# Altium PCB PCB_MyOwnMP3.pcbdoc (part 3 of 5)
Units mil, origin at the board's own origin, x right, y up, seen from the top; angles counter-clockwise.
Board outline 3605 x 4860 mil, 6 copper layers (Top Layer, Inner1, Inner2, Inner3, Inner4, Bottom Layer); 291 components, 261 nets, 1070 pads, 1658 vias.
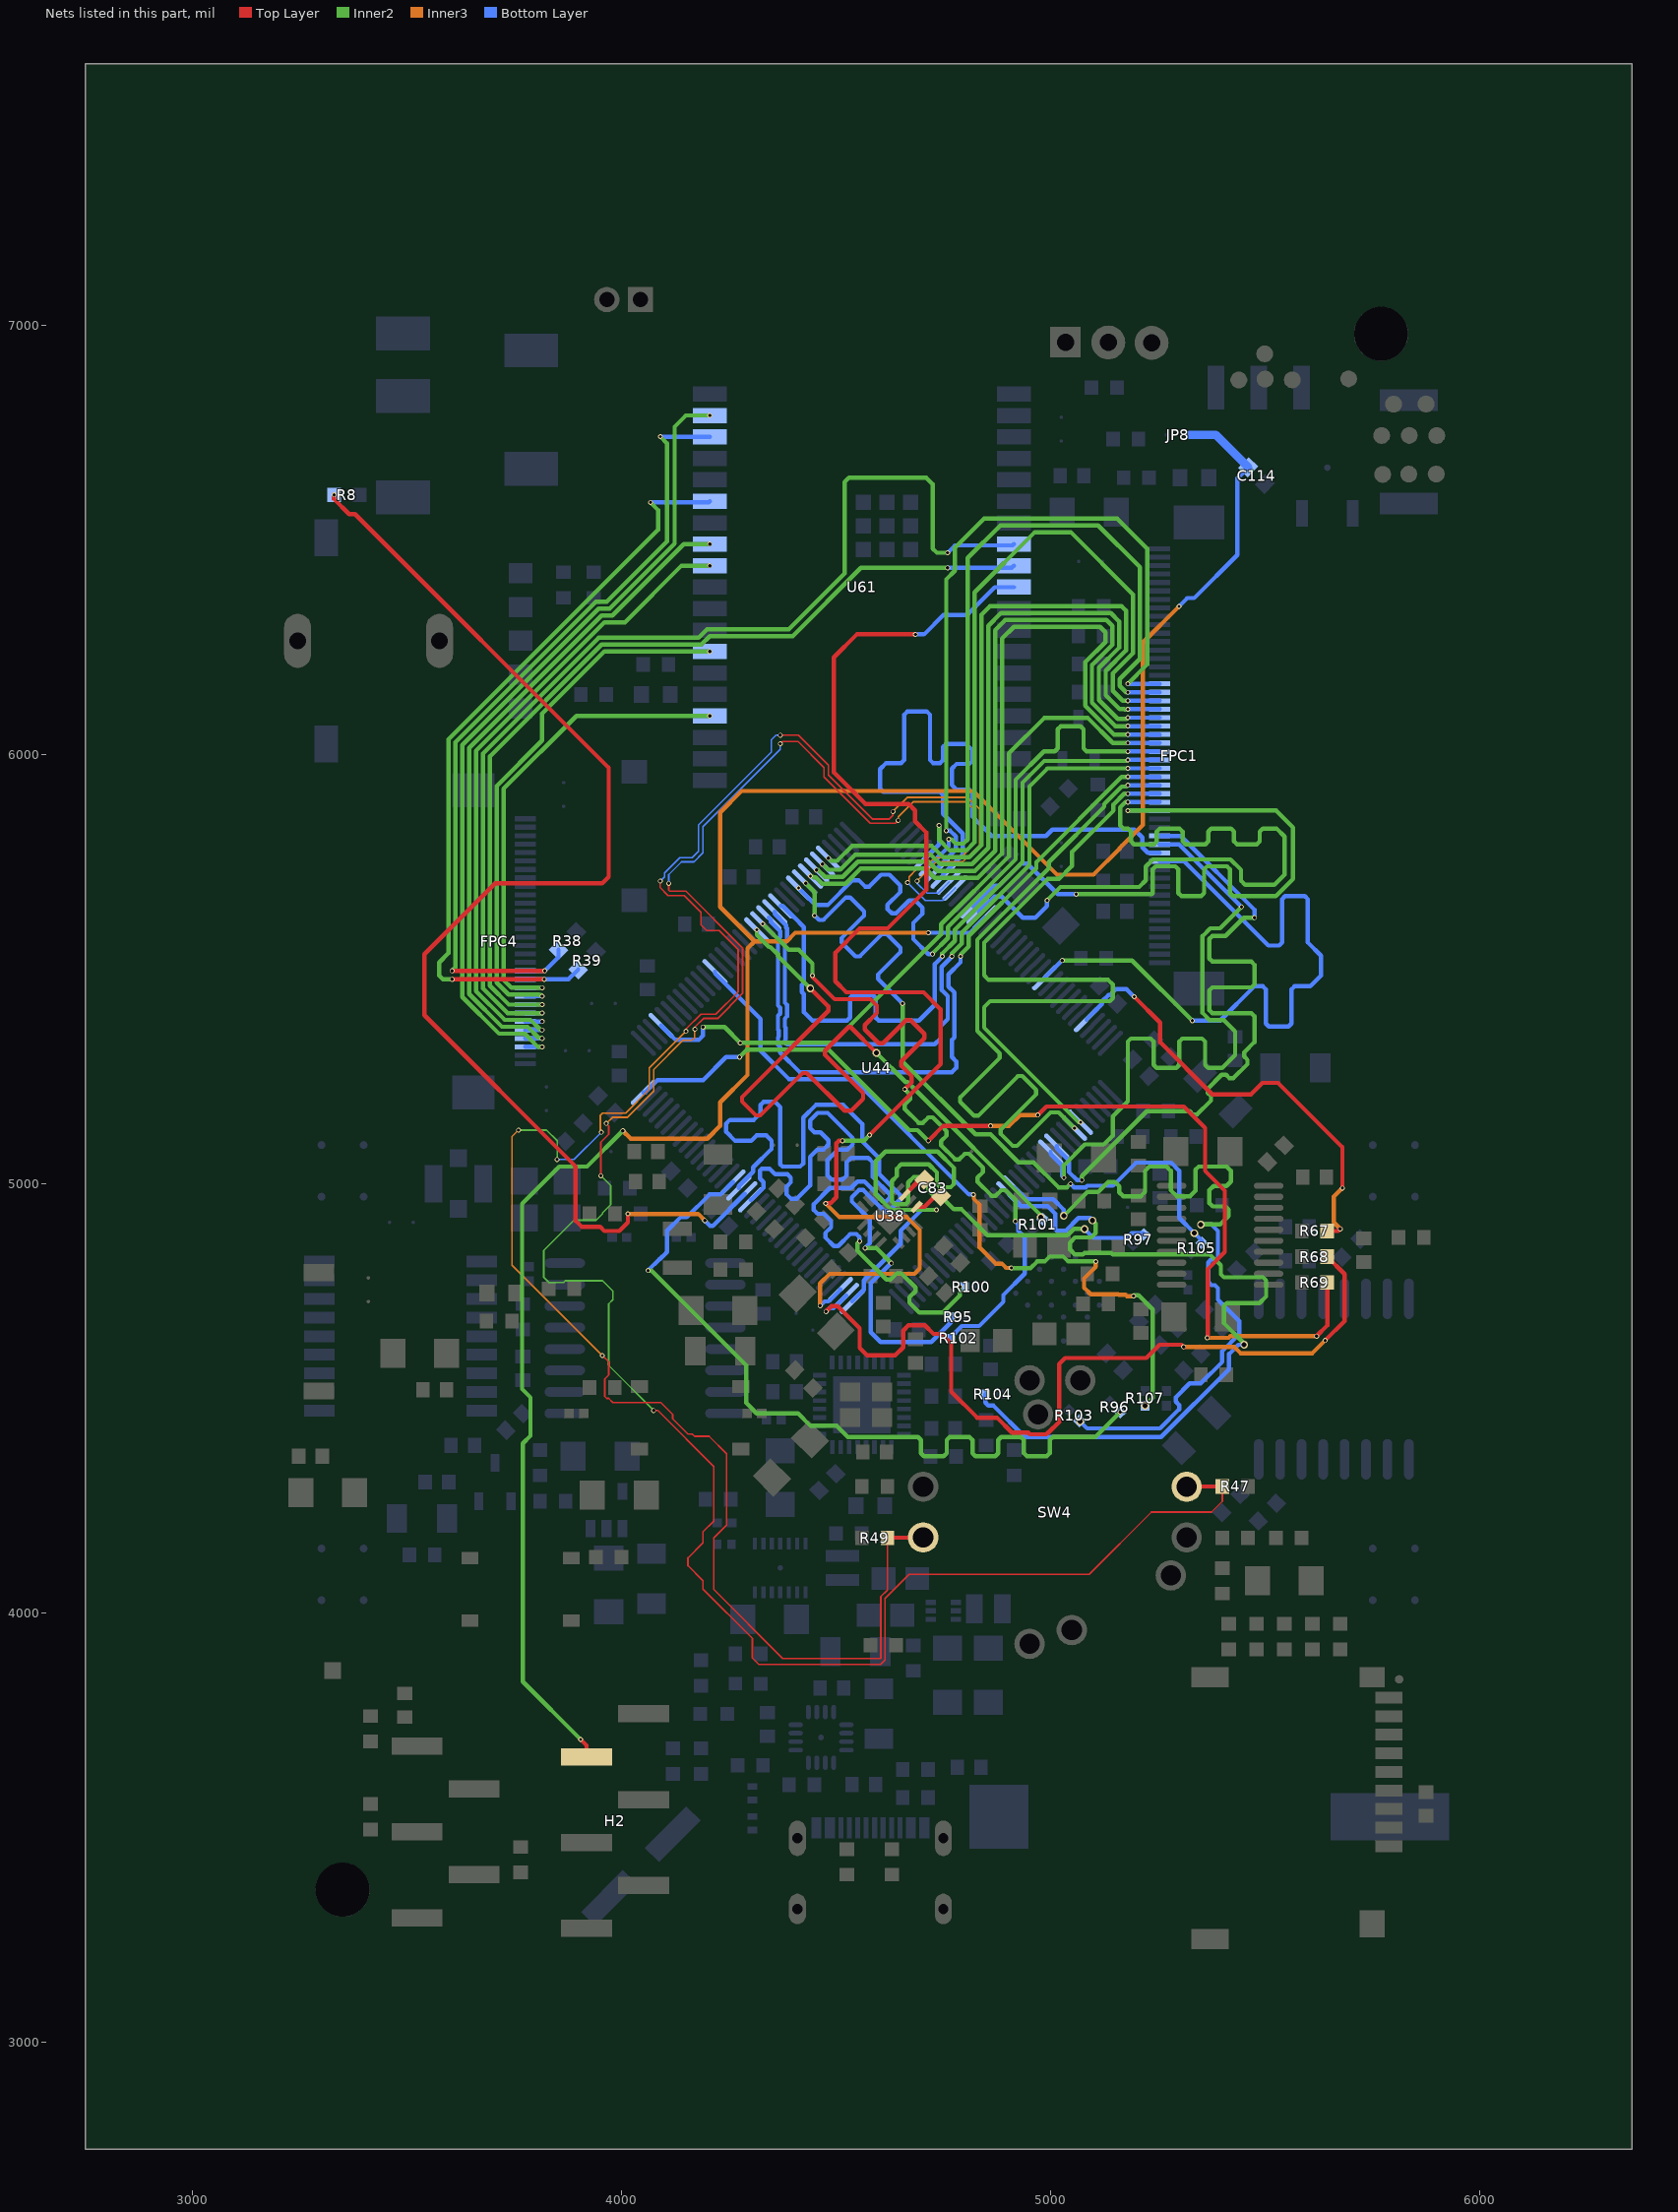
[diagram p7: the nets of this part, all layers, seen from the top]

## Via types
v1: diameter 11.42, hole 7.48, Top Layer to Bottom Layer, 1536 vias
v2: diameter 17.72, hole 11.81, Top Layer to Bottom Layer, 85 vias
v3: diameter 39.37, hole 29.53, Top Layer to Bottom Layer, 11 vias
v4: diameter 11.81, hole 7.87, Top Layer to Bottom Layer, 8 vias
v5: diameter 47.24, hole 23.62, Top Layer to Bottom Layer, 8 vias
v6: diameter 19.68, hole 11.81, Top Layer to Bottom Layer, 4 vias
v7: diameter 24.41, hole 12.2, Top Layer to Bottom Layer, 3 vias
v8: diameter 11.4, hole 7.5, Top Layer to Bottom Layer, 3 vias

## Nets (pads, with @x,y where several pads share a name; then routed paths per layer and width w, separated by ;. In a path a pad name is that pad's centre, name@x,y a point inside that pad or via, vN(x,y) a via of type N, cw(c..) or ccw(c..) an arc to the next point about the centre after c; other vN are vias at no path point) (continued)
CK#: R107.1 U44.49 | length 1785.5
  Inner2 w10: v1(4908.62,4803.99) 4909.38,4803.23 4953.03,4803.23 4968.81,4819.02 4986.07,4819.02 4997.45,4830.39 5029.61,4830.39 5040.98,4819.02 5104.96,4819.02 v1(5105.27,4818.7) ; v1(5193.31,4738.31) 5195,4740 5205,4740 5238.03,4706.97 5238.03,4500.99 v2(5220,4482.96)
  Inner3 w10: v1(4820,4975) 4821.11,4973.89 4821.11,4964.59 4834.62,4951.08 4834.62,4851.25 4871.88,4813.99 4886.45,4813.99 4896.45,4803.99 v1(4908.62,4803.99) ; v1(5105.27,4818.7) 5105.27,4806.52 5078.05,4779.29 5078.05,4757.74 5093.28,4742.51 5157.63,4742.51 5158.75,4741.38 5174.52,4741.38 5177.6,4738.31 v1(5193.31,4738.31)
  Bottom Layer w10: U44.49@4217.78,5494.1 4217.78,5490.04 4323.94,5383.88 4323.94,5310 4389.92,5244.02 4540.77,5244.02 4809.79,4975 v1(4820,4975)
CPN: C83.1 U38.9 | length 67.1
  Top Layer w10: U38.9@4687.62,4945.9 4705.74,4945.9 4730.35,4970.51 C83.1@4744.49,4970.51
CPP: C83.2 U38.11 | length 60.5
  Top Layer w10: U38.11@4659.83,4973.69 4695.63,5009.49 C83.2@4705.51,5009.49
CS1: FPC4.7 U61.8 | length 2545.3
  Inner2 w10: v1(3815,5397.68) 3734.51,5397.68 3677.05,5455.14 3677.05,6002.26 3946.76,6271.97 4179.36,6271.97 4199.36,6291.97 4390,6291.97 4520,6421.97 4520,6635 4530,6645 4710,6645 4725,6630 4725,6480 4735,6470 v1(4760,6470)
  Bottom Layer w10: FPC4.7@3775.53,5397.68 v1(3815,5397.68) ; v1(4760,6470) 4777.23,6487.23 4911.56,6487.23 U61.8@4914.33,6490
CS2: FPC4.8 U61.9 | length 2119.1
  Inner2 w10: v1(3815,5417.36) 3737.43,5417.36 3693.03,5461.76 3693.03,5995.64 3953.38,6255.98 4185.98,6255.98 4205.98,6275.98 4399.02,6275.98 4558.03,6435 v1(4760,6435)
  Bottom Layer w10: FPC4.8@3775.53,5417.36 v1(3815,5417.36) ; v1(4760,6435) 4909.33,6435 U61.9@4914.33,6440
CS3: FPC4.9 U61.26 | length 1279.7
  Inner2 w10: v1(3815,5437.05) 3812.01,5440.04 3808.09,5440.04 3807.38,5440.75 3736.65,5440.75 3709.02,5468.38 3709.02,5926.62 3815,6032.6 3815,6095 3960,6240 v1(4205.67,6240)
  Bottom Layer w10: FPC4.9@3775.53,5437.05 v1(3815,5437.05)
CS4: FPC4.10 U61.23 | length 1133.1
  Inner2 w10: v1(3815,5456.73) 3743.27,5456.73 3725,5475 3725,5920 3895,6090 v1(4205.67,6090)
  Bottom Layer w10: FPC4.10@3775.53,5456.73 v1(3815,5456.73)
CS#: R105.1 U44.64 | length 1823.8
  Inner2 w10: v1(4429.36,5700.11) 4450,5679.47 v1(4450,5625) ; v1(4655,5420) 4655,5285 4825,5115 4860,5115 4925,5050 4960,5050 5018.34,4991.66 5038.05,4991.66 v1(5046.39,5000)
  Bottom Layer w10: v1(4450,5625) 4460.36,5614.64 4470.36,5614.64 4522.86,5667.14 4532.86,5667.14 4565.29,5634.71 4565.29,5624.71 4512.79,5572.21 4512.79,5562.21 4545.21,5529.79 4555.21,5529.79 4607.71,5582.29 4617.71,5582.29 4650.14,5549.86 4650.14,5539.86 4597.64,5487.36 4597.64,5477.36 v1(4655,5420) ; v1(5046.39,5000) 5054.78,4991.61 5081.61,4991.61 5085.35,4995.35 5145.35,4995.35 5199.29,5049.29 5280.71,5049.29 5300,5030 5300,4920 v2(5335,4885) 5352.05,4867.95 R105.1@5352.05,4862.05
DAC_BCK: R69.2 U44.36 | length 2409
  Top Layer w10: v1(4715,5100) 4750,5135 v1(4860,5135) ; v1(4970,5160) 4990,5180 5310,5180 5360,5130 5360,5030 5405.98,4984.02 5405.98,4840.98 5366.69,4801.69 5366.69,4642.68 v1(5365,4640.98) ; v1(5620,4645) 5644.66,4669.66 R69.2@5644.66,4770
  Inner2 w10: v1(4275,5295) 4292.21,5312.21 4482.79,5312.21 4670,5125 4690,5125 v1(4715,5100)
  Inner3 w10: v1(4860,5135) 4903.32,5135 4928.32,5160 v1(4970,5160) ; v1(5365,4640.98) 5415,4640.98 5419.02,4645 v1(5620,4645)
  Bottom Layer w10: U44.36@4050.75,5212.93 4055.26,5212.93 4083.84,5241.51 4190.41,5241.51 4243.9,5295 v1(4275,5295)
DAC_DIN: R68.2 U44.2 | length 1946.1
  Top Layer w10: v1(4476.58,4702.21) 4489.43,4715.06 4503.57,4715.06 4555.04,4663.6 4555.04,4617.35 4572.28,4600.11 4637.72,4600.11 4656.3,4618.69 4656.3,4657.86 4668.44,4670 4707.09,4670 4726.96,4650.13 4746.52,4650.13 4768.41,4628.24 4768.41,4515.37 4828.78,4455 4875,4455 4910,4420 4947.55,4420 4951.4,4416.14 4989.86,4416.14 4993.71,4420 4995,4420 5020,4445 5020,4580 5034.02,4594.02 5223.18,4594.02 5254.16,4625 5305,4625 v1(5310,4620) ; v1(5640,4635) 5685,4680 5685,4789.66 R68.2@5644.66,4830
  Inner3 w10: v1(5310,4620) 5427.92,4620 5442.77,4605.16 5610.16,4605.16 v1(5640,4635)
  Bottom Layer w10: v1(4476.58,4702.21) 4484.37,4710 4494.34,4710 U44.2@4524.01,4739.67
DAC_LRCK: R67.2 U44.104 | length 1067.4
  Top Layer w10: v1(5195,5435.72) 5255,5375.72 5255,5330 5376.69,5208.31 5466.91,5208.31 5493.61,5235 5530,5235 5680,5085 v1(5680,4990) ; R67.2@5644.66,4890 5670,4890 v1(5675,4895)
  Inner3 w10: v1(5675,4895) 5660,4910 5660,4970 v1(5680,4990)
  Bottom Layer w10: U44.104@5083.58,5382.75 5120,5419.17 5120,5425 5135,5440 5138.96,5440 5152.22,5453.26 5176.74,5453.26 5194.28,5435.72 v1(5195,5435.72)
DETECT: R8.1 U44.19 | length 2908.8
  Top Layer w10: v1(3330,6605) 3330,6595 3365,6560 3379.14,6560 3970,5969.14 3970,5715 3955,5700 3705.83,5700 3540.83,5535 3540.83,5392.55 3893.15,5040.22 3893.15,4913.77 3906.92,4900 3950,4900 3960,4890 3995,4890 4015,4910 v1(4015,4929.8)
  Inner3 w10: v1(4015,4929.8) 4178.61,4929.8 v1(4194.16,4914.25)
  Bottom Layer w10: v1(4194.16,4914.25) 4206.52,4901.89 4213.06,4901.89 U44.19@4287.38,4976.21
DQ0: R95.2 U44.20 | length 1906.6
  Inner2 w10: v1(4567.63,4850.06) 4593.73,4850.06 v1(4628.81,4814.98)
  Bottom Layer w10: U44.20@4273.46,4990.22 4273.46,4994.72 4306.94,5028.21 4306.94,5038.48 4349.66,5081.2 4349.66,5100.34 4337.45,5112.55 4314.75,5112.55 4302.19,5100 4265,5100 4243.75,5121.25 4243.75,5140 4252.51,5148.75 4308.46,5148.75 4324.2,5164.5 4324.2,5184.2 4331.09,5191.09 4357.55,5191.09 4370,5178.63 4370,5045 4375,5040 4416.39,5040 4423.46,5047.07 4423.46,5154.12 4452.99,5183.65 4516.64,5183.65 4561.27,5139.01 4561.27,5098.73 4600.98,5059.02 4600.98,5022.5 4649.81,4973.67 4649.81,4963.67 4622.39,4936.25 4612.39,4936.25 4563.37,4985.27 4553.37,4985.27 4536.66,4968.56 4536.66,4958.56 4578.61,4916.61 4578.61,4861.04 v1(4567.63,4850.06) ; v1(4628.81,4814.98) 4627.8,4814.98 4580.98,4768.16 4580.98,4654.02 4603.7,4631.3 4721.96,4631.3 4767.96,4677.3 R95.2@4767.96,4690
DQ1: R96.2 U44.21 | length 1867.8
  Inner2 w10: v1(4062.16,4797.84) 4069.55,4797.84 4290.47,4576.92 4290.47,4489.53 4315,4465 4411.4,4465 4440.41,4435.98 4501.62,4435.98 4527.61,4410 4690.76,4410 4697.83,4402.93 4697.83,4372.07 4704.9,4365 4750.76,4365 4757.83,4372.07 4757.83,4402.93 4764.9,4410 4810.76,4410 4817.83,4402.93 4817.83,4372.07 4824.9,4365 4870.76,4365 4877.83,4372.07 4877.83,4402.93 4884.9,4410 4930.76,4410 4937.83,4402.93 4937.83,4372.07 4944.9,4365 4990.76,4365 4997.83,4372.07 4997.83,4402.93 5004.9,4410 5104.1,4410 v1(5162.05,4467.95)
  Bottom Layer w10: v1(4062.16,4797.84) 4088.03,4823.71 4088.71,4823.71 4105.24,4840.24 4105.24,4840.92 4105.84,4841.52 4105.84,4890.18 4137.51,4921.85 4151.85,4921.85 4205,4975 4230.41,4975 U44.21@4259.54,5004.13
DQ2: R97.2 U44.1 | length 1783.1
  Inner2 w10: v1(4734.13,4939.28) 4628.33,4939.28 4592.11,4975.5 4592.11,5052.11 4615,5075 4736.73,5075 4775,5036.73 4775,4999.75 4767.05,4991.79 4742.07,4991.79 4735,4998.86 4735,5026.35 4716.35,5045 4651.62,5045 4641.86,5035.24 4641.86,5018.25 4630,5006.39 4630,4959.2 4637.13,4952.07 4662.07,4952.07 4667.93,4957.93 4667.93,5002.93 4681.04,5016.04 4701.81,5016.04 4715,5002.85 4715,4985 4725,4975 4740,4975 4774.4,4940.6 4792.49,4940.6 4852.75,4880.33 5039.67,4880.33 5054.33,4895 5078.54,4895 v2(5078.85,4894.69)
  Bottom Layer w10: U44.1@4537.93,4725.75 4565,4752.82 4565,4774.78 4650.98,4860.77 4650.98,4890.77 4699.49,4939.28 v1(4734.13,4939.28) ; v2(5078.85,4894.69) 5099.6,4873.94 5178.37,4873.94 5188.76,4884.33 5214.77,4884.33 R97.2@5217.05,4882.05
DQ3: R100.2 U44.18 | length 1845.4
  Inner2 w10: v1(4554.8,4866.32) 4549.8,4861.32 4549.8,4844.28 4617.36,4776.71 4627.36,4776.71 4641.99,4791.34 4651.99,4791.34 4685,4758.33 4685,4749.49 4670.98,4735.48 4670.98,4723.09 4694.08,4700 4748.67,4700 4788.26,4739.58 v1@4788.26,4759.95
  Bottom Layer w10: U44.18@4301.3,4962.38 4302.38,4962.38 4330.86,4990.86 4330.86,5004.03 4322.93,5011.96 4322.93,5030.98 4326.95,5035 4345,5035 4357.93,5022.07 4386.72,5022.07 4394.33,5014.45 4394.33,5003.24 4385,4993.91 4385,4975 4394.73,4965.27 4408.87,4965.27 4439.45,4995.84 4439.45,5062.5 4456.95,5080 4471.09,5080 4482.34,5091.25 4482.34,5101.25 4463.59,5120 4449.45,5120 4439.45,5130 4439.45,5147.5 4456.95,5165 4480.36,5165 4538.93,5106.43 4538.93,5091.93 4527,5080 4505,5080 4480,5055 4480,5019.31 4490,5009.31 4515,5009.31 4525,5019.31 4525,5050.36 4535,5060.36 4575,5060.36 4585,5050.36 4585,5015.88 4625.33,4975.55 4625.33,4967.77 4616.36,4958.81 4612.43,4958.81 4566.24,5005 4550,5005 4535,4990 4485.82,4990 4448.11,4952.29 4448.11,4938.96 4457.07,4930 4471.21,4930 4488.54,4912.68 4488.54,4898.54 4475,4885 4475,4875 4495,4855 4505,4855 4533.06,4883.06 4547.2,4883.06 4554.8,4875.46 v1(4554.8,4866.32)
  other v1: 4788.31,4760
DQ4: R101.2 U44.56 | length 1799.6
  Top Layer w10: v2(4440,5455) 4482.03,5412.97 4482.03,5402.97 4280.81,5201.76 4280.81,5191.76 4313.24,5159.33 4323.24,5159.33 4421.89,5257.98 4431.89,5257.98 4519.88,5170 4535.27,5170 4562.93,5197.66 4562.93,5211.8 4474.32,5300.41 4474.32,5310.41 4529,5365.09 4534,5365.09 v2(4594.1,5305)
  Inner2 w10: v1(4315.22,5591.54) 4315.22,5579.78 4343.31,5551.69 4346.91,5551.69 4365,5533.61 4365,5530 v2(4440,5455) ; v2(4594.1,5305) 4662.41,5236.69 4666.91,5236.69 4977.05,4926.56 v2(4977.05,4922.05)
DQ5: R102.2 U44.57 | length 1722.8
  Top Layer w10: v1(4445,5485) 4445,5481.7 4496.7,5430 4580,5430 4595,5415 4595,5397.75 4566.98,5369.73 4566.98,5359.73 4599.4,5327.3 4609.4,5327.3 4663.55,5381.45 4673.55,5381.45 4705.98,5349.02 4705.98,5339.02 4651.83,5284.87 4651.83,5274.87 4676.28,5250.42 4676.28,5236.28 v1(4660,5220)
  Inner2 w10: v1(4329.13,5605.46) 4389.59,5545 4413.06,5545 4445,5513.06 v1(4445,5485) ; v1(4660,5220) 4672.84,5207.16 4672.84,5197.16 4660.01,5184.33 4660.01,5174.33 4692.44,5141.9 4702.44,5141.9 4715.27,5154.73 4725.27,5154.73 4757.7,5122.3 4757.7,5112.3 4744.86,5099.47 4744.86,5089.47 4777.29,5057.05 4787.29,5057.05 4800.12,5069.88 4810.12,5069.88 4842.55,5037.45 4842.55,5027.45 4829.72,5014.62 4829.72,5004.62 4862.14,4972.19 4872.14,4972.19 4884.97,4985.03 4894.97,4985.03 4917.87,4962.13 v1(4917.87,4912.5)
  Bottom Layer w10: R102.2@4767.96,4640 4766.35,4641.61 4793.13,4668.39 4833.39,4668.39 4890,4725 4890,4740.8 4940,4790.8 4940,4875 4925,4890 4925,4905.37 v1(4917.87,4912.5)
DQ6: R103.2 U44.125 | length 1867.8
  Inner2 w10: v2(5030.64,4925.47) 5086.15,4980.98 5110.98,4980.98 5134.02,5004.02 5150,5004.02 5160,4994.02 5160,4980 5169.02,4970.98 5210,4970.98 5220,4980.98 5220,5030 5230,5040 5270,5040 5280,5030 5280,4985 5294.02,4970.98 5325,4970.98 5337.93,4983.91 5337.93,5032.93 5345,5040 5410,5040 5420,5030 5420,5005 5410,4995 5380,4995 5370,4985 5370,4955 5377.93,4947.07 5407.93,4947.07 5415,4940 5415,4925 5395,4905 v2(5350,4905)
  Bottom Layer w10: U44.125@4916.54,4990.22 4943.07,4963.69 5006.31,4963.69 5030.64,4939.36 v2(5030.64,4925.47) ; v2(5068.92,4446.08) 5085,4430 5255,4430 5299.45,4474.45 5299.45,4484.45 5291.61,4492.28 5291.61,4502.28 5324.04,4534.71 5349.71,4534.71 5400,4585 5400,4610 5440,4650 5440,4680 5390,4730 5390,4756.78 5382.93,4763.85 5374.42,4763.85 5367.35,4770.92 5367.35,4816.78 5374.42,4823.85 5386.25,4823.85 5390,4827.61 5390,4890 5375,4905 v2(5350,4905)
DQ7: R104.2 U44.126 | length 1906.4
  Inner2 w10: v2(5097.55,4914.46) 5105,4907.02 5105,4885 5094.84,4874.84 5056.78,4874.84 5045,4863.06 5045,4846.94 5056.82,4835.12 5075.12,4835.12 5078.96,4838.96 5141.04,4838.96 5144.88,4835.12 5371.66,4835.12 5396.78,4810 5396.78,4789.02 5403.85,4781.95 5495.22,4781.95 5502.29,4774.88 5502.29,4737.29 5486.95,4721.95 5410.92,4721.95 5403.85,4714.88 5403.85,4675.18 5450.98,4628.05 v2(5450.98,4625)
  Bottom Layer w10: R104.2@4847.96,4510 4847.96,4490 4855.03,4482.93 4867.07,4482.93 4940,4410 5257.61,4410 5415.98,4568.38 5415.98,4603.38 5437.61,4625 v2(5450.98,4625) ; U44.126@4902.62,4976.3 4931.21,4947.71 4993.09,4947.71 5010.79,4930 5010.79,4894.21 5014.17,4890.83 5035.83,4890.83 5065,4920 5092.02,4920 v2@5097.53,4914.49
ENC_A: R49.1 SW4.8 U44.81 | length 4820.5
  Top Layer w3.94: v1(3955,4600) 3970,4585 3970,4554.47 3960.83,4545.3 3960.83,4504.7 3965.49,4500.04 3970,4500.04 ; 3970,4500 3980,4490 4091.68,4490 4119.37,4462.31 4119.37,4452.31 4154.63,4417.05 4164.63,4417.05 4169.97,4411.71 4203.96,4411.71 4245,4370.68 4245,4205 4215,4175 4215,4055 4375.83,3894.17 4604.17,3894.17 4604.17,4038.2 4619.66,4053.69 R49.1@4619.66,4175 ; v1(4090.04,5704.96) 4090.04,5690.22 4108.67,5671.59 4146.06,5671.59 4185,5632.65 4185,5603.24 4198.24,5590 4227.65,5590 4271.99,5545.66 4271.99,5447.16 4219.8,5394.96 4184.96,5394.96 4150,5360 v1(4150,5355) ; v1(4370,6045) 4412.05,6045 4482.05,5975 4482.05,5951.98 4584.11,5849.92 4624.44,5849.92 4632.68,5858.16 v1(4632.68,5867.32)
  Top Layer w10: R49.1@4619.6,4175 SW4.8@4702.91,4175.94
  Inner2 w3.94: v1(3760,5125) 3825,5125 3850,5100 v1(3850,5056.69)
  Inner3 w3.94: v1(3760,5125) 3745,5110 3745,4810 v1(3955,4600) ; v1(3952.95,5120) 3950.83,5122.12 3950.83,5159.73 3955.55,5164.45 4009.45,5164.45 4065,5220 4065,5270 v1(4150,5355) ; v1(4632.68,5867.32) 4665.36,5900 4807.05,5900 4835,5872.05 4835,5790 4795,5750 4733.65,5750 v1(4688.88,5705.23)
  Bottom Layer w3.94: v1(3850,5056.69) 3889.65,5056.69 v1(3952.95,5120) ; v1(4090.04,5704.96) 4100.08,5715 4100.08,5724.11 4135.89,5759.92 4164.63,5759.92 4179.7,5775 4179.7,5836.08 4349.31,6005.69 4349.31,6034.31 4360,6045 v1(4370,6045) ; v1(4688.88,5705.23) 4688.88,5700.15 4712.02,5677.02 4737.55,5677.02 U44.81@4763.43,5702.9
ENC_B: R47.1 SW4.7 U44.82 | length 5450.3
  Top Layer w3.94: v1(3951.69,5018.7) 3951.69,5096.69 3970,5115 3970,5135 v1(3964.5,5140.5) ; v1(4075,4471.69) 4084.78,4471.69 4215.12,4341.35 4215.12,4214.15 4190.08,4189.11 4190.08,4163.46 4155,4128.38 4155,4110 4190,4075 4190,4055.97 4305,3940.97 4305,3895 4319.92,3880.08 4604.11,3880.08 4614.09,3890.06 4614.09,4034.09 4670,4090 5090,4090 5235,4235 5375,4235 5400.34,4260.34 R47.1@5400.34,4295 ; v1(4110,5700) 4110,5684.29 4112.78,5681.51 4150.17,5681.51 4281.91,5549.77 4281.91,5443.05 4223.91,5385.04 4190.72,5385.04 4171.34,5365.66 v1(4171.34,5360.02) ; v1(4370,6025) 4375.08,6030.08 4411.51,6030.08 4472.13,5969.46 4472.13,5947.87 4580,5840 4638.31,5840 v1(4645,5846.69)
  Top Layer w10: SW4.7@5317.1,4294.1 R47.1@5400.34,4295
  Inner2 w3.94: 3818.5,4784.61 3818.59,4784.52 ; v1(3951.69,5018.7) 3974.65,4995.75 3974.65,4951.5 3955.51,4932.36 3955.51,4930 3940.51,4915 3889.49,4915 3818.59,4844.1 3818.59,4784.52 ; v1(4075,4471.69) 3970,4576.69 3970,4720 3980,4730 3980,4750 3955.89,4774.11 3869.11,4774.11 3865,4770 3830.93,4770 3818.59,4782.33 3818.59,4784.52
  Inner3 w3.94: v1(3964.5,5140.5) 3978.52,5154.53 4013.56,5154.53 4074.92,5215.89 4074.92,5265.89 4143.12,5334.09 4164.09,5334.09 4170,5340 4170,5358.68 v1(4171.34,5360.02) ; v1(4645,5846.69) 4645,5855 4679.65,5889.65 4803.37,5889.65 4825.08,5867.94 4825.08,5794.52 4790.48,5759.92 4729.54,5759.92 4702.31,5732.69 4687.69,5732.69 4670,5715 4670,5705 v1(4666.54,5701.54)
  Bottom Layer w3.94: v1(4110,5700) 4110,5720 4140,5750 4168.74,5750 4189.63,5770.89 4189.63,5831.97 4370,6012.35 v1(4370,6025) ; v1(4666.54,5701.54) 4708.07,5660 4748.38,5660 U44.82@4777.35,5688.97
ESP32_EN: C114.2 H2.5 JP8.2 U44.87 | length 5520.2
  Top Layer w10: v1(3905,3705) 3918.46,3691.54 H2.5@3918.46,3665
  Inner2 w10: v1(3905,3705) 3770,3840 3770,4395 3787.94,4412.94 3787.94,4502.06 3768.31,4521.69 3768.31,4953.31 3855,5040 3919.78,5040 v1(4003.09,5123.31)
  Inner3 w10: v1(4003.09,5123.31) 4021.51,5104.89 4199.89,5104.89 4230,5135 4230,5190 4293.5,5253.5 4293.5,5548.5 4310,5565 ; v1(4715.26,5584.8) 4404.8,5584.8 4385,5565 4310,5565 ; v1(5299.02,6345) 5215,6260.98 5215,5836.05 5160.87,5781.91 5160.87,5780.87 5100,5720 5015,5720 4820,5915 4280,5915 4230,5865 4230,5645 4310,5565
  Bottom Layer w10: v1(4715.26,5584.8) 4812.36,5584.8 U44.87@4846.94,5619.38 ; v1(5299.02,6345) 5318.54,6364.53 5334.53,6364.53 5435,6465 5435,6643.98 C114.2@5460.51,6669.49
  Bottom Layer w19.68: JP8.2@5324.53,6745 5385,6745 C114.2@5460.51,6669.49
ESP_CS: FPC4.6 | length 39.5
  Bottom Layer w10: FPC4.6@3775.53,5377.99 v1(3815,5377.99)
ESP_MISO: FPC4.4 U61.31 | length 1583
  Inner2 w10: v1(3815,5338.62) 3813.62,5340 3806.78,5340 3781.07,5365.71 3721.26,5365.71 3645.08,5441.9 3645.08,6015.5 3953.52,6323.94 3978.94,6323.94 4145,6490 4205.43,6490 v1(4205.67,6490.24)
  Bottom Layer w10: FPC4.4@3775.53,5338.62 v1(3815,5338.62)
ESP_MOSI: FPC4.3 U61.37 | length 1914.6
  Inner2 w10: v1(3815,5318.94) 3805.23,5318.94 3774.45,5349.73 3714.64,5349.73 3629.1,5435.28 3629.1,6022.12 3946.9,6339.92 3972.32,6339.92 4123.7,6491.3 4123.7,6763.7 4150,6790 v1(4205.67,6790)
  Bottom Layer w10: FPC4.3@3775.53,5318.94 v1(3815,5318.94)
ESP_SCK: FPC4.5 U61.30 | length 1514.3
  Inner2 w10: v1(3815,5358.31) 3811.07,5358.31 3787.69,5381.7 3727.88,5381.7 3661.06,5448.52 3661.06,6008.88 3960.14,6307.95 4007.95,6307.95 4140,6440 v1(4205.67,6440)
  Bottom Layer w10: FPC4.5@3775.53,5358.31 v1(3815,5358.31)
ESP_SCL: FPC4.12 R38.2 U61.36 | length 1912.7
  Top Layer w10: v1(3605,5496.1) v1(3821.1,5496.1)
  Inner2 w10: v1(3605,5496.1) 3613.11,5504.21 3613.11,6028.74 3940.28,6355.9 3965.69,6355.9 4106.25,6496.46 4106.25,6725 v1(4090.63,6740.63)
  Bottom Layer w10: FPC4.12@3775.53,5496.1 v1(3821.1,5496.1) 3853.1,5528.1 R38.2@3853.07,5544.99 ; v1(4090.63,6740.63) 4091.25,6740 U61.36@4205.67,6740
ESP_SDA: FPC4.11 R39.2 U61.33 | length 1841.7
  Top Layer w10: v1(3605,5476.4) v1(3820.09,5476.4)
  Inner2 w10: v1(3605,5476.4) 3583.6,5476.4 3575,5485 3575,5515.37 3597.13,5537.5 3597.13,6035.36 4085,6523.23 4085,6570 v1(4067.5,6587.5)
  Bottom Layer w10: FPC4.11@3775.53,5476.42 v1(3820.09,5476.4) 3876.4,5476.4 R39.2@3899.03,5499.03 ; v1(4067.5,6587.5) 4203.17,6587.5 U61.33@4205.67,6590
FMC_A16: FPC1.37 U44.80 | length 1639.3
  Bottom Layer w10: U44.80@4749.51,5716.81 4749.51,5721.05 4795.18,5766.72 4795.18,5816.03 4749.51,5861.7 4749.51,5906.12 4742.44,5913.19 4609.62,5913.19 4602.55,5920.26 4602.55,5966.12 4616.69,5980.26 4651.85,5980.26 4658.92,5987.33 4658.92,6092.93 4665.99,6100 4711.85,6100 4718.92,6092.93 4718.92,5987.33 4725.99,5980.26 4742.44,5980.26 4749.51,5987.33 4749.51,6017.93 4756.58,6025 4802.93,6025 4817.93,6010 4817.93,5985.25 4810.86,5978.18 4780.89,5978.18 4770,5967.29 4770,5929.08 4780.89,5918.18 4810.86,5918.18 4817.93,5911.11 4817.93,5855.51 4863.44,5810 4988.94,5810 5004.14,5825.2 5195.13,5825.2 5213.76,5806.57 5213.76,5783.85 5226.62,5770.98 FPC1.37@5254.35,5770.98
FMC_D0: FPC1.32 U44.85 | length 1672.3
  Inner2 w10: v1(5059.49,5674.74) 5235.45,5674.74 5237.79,5677.07 5237.79,5732.62 5244.86,5739.69 5290.72,5739.69 5297.79,5732.62 5297.79,5677.07 5304.86,5670 5350.72,5670 5357.79,5677.07 5357.79,5732.62 5364.86,5739.69 5410.72,5739.69 5417.79,5732.62 5417.79,5677.07 5424.86,5670 5525,5670 5565,5710 5565,5830 5525.59,5869.41 v1(5180,5869.41)
  Bottom Layer w10: U44.85@4819.1,5647.22 4866.41,5694.53 4879.53,5694.53 4931.13,5746.13 4945.27,5746.13 5016.66,5674.74 v1(5059.49,5674.74) ; v1(5180,5869.41) FPC1.32@5254.35,5869.41
FMC_D1: FPC1.31 U44.86 | length 1672.5
  Inner2 w10: v1(4991.69,5660.22) 5022.9,5691.43 5206.43,5691.43 5221.8,5706.8 5221.8,5739.24 5238.24,5755.67 5419.33,5755.67 5443.7,5731.3 5443.7,5706.15 5453.62,5696.23 5521.23,5696.23 5545,5720 5545,5809.02 5526.3,5827.72 5494.56,5827.72 5487.48,5820.65 5487.48,5797.83 5480.41,5790.76 5434.56,5790.76 5427.48,5797.83 5427.48,5820.65 5420.41,5827.72 5374.56,5827.72 5367.48,5820.65 5367.48,5797.83 5360.41,5790.76 5314.56,5790.76 5307.48,5797.83 5307.48,5820.65 5300.41,5827.72 5254.56,5827.72 5247.48,5820.65 5247.48,5797.83 5240.41,5790.76 5194.56,5790.76 5187.48,5797.83 5187.48,5820.65 5180.41,5827.72 5169.49,5827.72 5162.42,5834.79 5162.42,5877 5174.51,5889.09 v1(5180,5889.09)
  Bottom Layer w10: U44.86@4833.03,5633.3 4868.91,5669.18 4885.82,5669.18 4935,5620 4964.19,5620 4991.69,5647.5 v1(4991.69,5660.22) ; v1(5180,5889.09) FPC1.31@5254.35,5889.09
FMC_D2: FPC1.30 U44.114 | length 1669.5
  Inner2 w10: v1(5069.65,5143.33) 5065.43,5143.33 4845,5363.76 4845,5411.38 4859.14,5425.52 5137.9,5425.52 5144.97,5432.59 5144.97,5464.31 5134.28,5475 4855.52,5475 4845,5485.52 4845,5561.84 4993.16,5710 5019.48,5710 5050,5740.52 5050,5773.04 5146.44,5869.48 5146.44,5883.62 5171.59,5908.78 v1(5180,5908.78)
  Bottom Layer w10: v1(5180,5908.78) FPC1.30@5254.35,5908.78
FMC_D3: FPC1.29 U44.115 | length 1634.4
  Inner2 w10: v1(5055.74,5129.41) 5018.91,5166.24 4999.85,5166.24 4921.8,5088.2 4911.8,5088.2 4883.91,5116.09 4883.91,5126.09 4966.48,5208.67 4966.48,5218.67 4934.06,5251.09 4924.06,5251.09 4831.48,5158.52 4821.48,5158.52 4789.06,5190.94 4789.06,5200.94 4881.63,5293.52 4881.63,5303.52 4829.02,5356.13 4829.02,5568.46 4995.82,5735.27 4995.82,5749.41 5125,5878.58 5125,5884.79 5165.68,5925.47 5177.01,5925.47 v1(5180,5928.46)
  Bottom Layer w10: v1(5180,5928.46) FPC1.29@5254.35,5928.46
FMC_D4: FPC1.28 U44.58 | length 1715
  Inner2 w10: v1(4790,5530) 4790,5533.95 4808.94,5552.89 4808.94,5577.19 4966.61,5734.86 4966.61,5749 5165.75,5948.15 v1(5180,5948.15)
  Bottom Layer w10: U44.58@4343.06,5619.38 4348.06,5614.38 4348.06,5610.14 4350.82,5607.37 4350.82,5607.1 4369.57,5588.35 4369.57,5574.69 4364.57,5569.69 4364.57,5415.26 4369.57,5410.26 4369.57,5396.43 4364.57,5391.43 4364.57,5359.04 4366.69,5356.91 4366.69,5343.09 4364.57,5340.96 4364.57,5323.38 4369.57,5318.38 4369.57,5305.43 4415,5260 4770,5260 4780.08,5270.08 4780.08,5284.92 4770,5295 4770,5335 4776.16,5341.16 4776.16,5445.23 4761.97,5459.42 4761.97,5487.83 4790,5515.86 v1(4790,5530) ; v1(5180,5948.15) FPC1.28@5254.35,5948.15
FMC_D5: FPC1.27 U44.59 | length 1699.6
  Inner2 w10: v1(4770,5530) 4770,5536.56 4792.95,5559.51 4792.95,5585.02 4950.62,5742.69 4950.62,5925.62 4992.83,5967.83 v1(5180,5967.83)
  Bottom Layer w10: U44.59@4356.97,5633.3 4356.97,5628.8 4383.5,5602.27 4383.5,5597.03 4385.55,5594.97 4385.55,5568.06 4380.55,5563.06 4380.55,5421.88 4385.55,5416.88 4385.55,5389.81 4380.55,5384.81 4380.55,5365.66 4382.68,5363.54 4382.68,5336.46 4380.55,5334.34 4380.55,5330 4385.55,5325 4730,5325 4744.09,5339.09 4744.09,5367.3 4760.18,5383.38 4760.18,5437.43 4745.98,5451.62 4745.98,5504.98 4770,5528.99 v1(4770,5530) ; v1(5180,5967.83) FPC1.27@5254.35,5967.83
FMC_D6: FPC1.26 U44.60 | length 1652.9
  Inner2 w10: v1(4747.4,5530) 4747.4,5536.56 4776.97,5566.13 4776.97,5591.64 4934.64,5749.31 4934.64,5934.64 4985,5985 5177.48,5985 v1(5180,5987.52)
  Bottom Layer w10: U44.60@4370.9,5647.22 4375.4,5647.22 4401.92,5620.7 4402.42,5620.7 4425,5598.12 4425,5468.06 4420.16,5463.22 4420.16,5446.78 4425,5441.94 4425,5400 4445,5380 4525.43,5380 4532.5,5387.07 4532.5,5432.93 4539.57,5440 4585.43,5440 4592.5,5432.93 4592.5,5387.07 4599.57,5380 4693.39,5380 4730,5416.61 4730,5511.6 4747.4,5529 v1(4747.4,5530) ; v1(5180,5987.52) FPC1.26@5254.35,5987.52
FMC_D7: FPC1.25 U44.63 | length 1569.6
  Inner2 w10: v1(4725,5535) 4725,5536.77 4760.98,5572.75 4760.98,5598.26 4918.65,5755.93 4918.65,5941.26 4984.59,6007.2 5009.59,6007.2 5016.67,6014.27 5016.67,6058.88 5023.74,6065.95 5069.59,6065.95 5076.67,6058.88 5076.67,6014.27 5083.74,6007.2 v1(5180,6007.2)
  Bottom Layer w10: v1(4412.65,5688.97) 4452.31,5649.31 4480.6,5649.31 4538.58,5707.28 4552.72,5707.28 4567.57,5692.43 4577.57,5692.43 4605.15,5720 4624.31,5720 4650,5694.31 4650,5680 4620,5650 4620,5640 4630,5630 4640,5630 4670,5660 4684.31,5660 4701.53,5642.78 4701.53,5629.31 4680,5607.78 4680,5570 4715,5535 v1(4725,5535) ; v1(5180,6007.2) FPC1.25@5254.35,6007.2
FMC_D8: FPC1.24 U44.40 | length 1707.4
  Inner2 w10: v1(4190,5365) 4240,5365 v1(4276.8,5328.2) 4492.1,5328.2 4745,5581.1 4745,5604.88 4902.67,5762.55 4902.67,6002.67 4985,6085 5086.9,6085 5145.01,6026.89 v1(5180,6026.89)
  Bottom Layer w10: U44.40@4092.51,5368.83 4126.34,5335 4180,5335 4190,5345 v1(4190,5365) ; v1(5180,6026.89) FPC1.24@5254.35,6026.89
FMC_D9: FPC1.23 U44.65 | length 1651.2
  Inner2 w10: v1(4440.49,5716.81) 4444.73,5716.81 4447.5,5714.05 4452.72,5714.05 4467.75,5699.02 4522.1,5699.02 4557.39,5734.3 4708.21,5734.3 4729.93,5712.58 4830.09,5712.58 4886.69,5769.17 4886.69,6269.84 4914.28,6297.43 5115.23,6297.43 5127.66,6285 5127.66,6262.16 5081.06,6215.56 5081.06,6214.65 5080.44,6214.03 5080.44,6114.06 5147.94,6046.57 v1(5180,6046.57)
  Bottom Layer w10: v1(5180,6046.57) FPC1.23@5254.35,6046.57
FMC_D10: FPC1.22 U44.66 | length 1647.5
  Inner2 w10: v1(4454.41,5730.74) 4458.63,5730.74 4474.37,5715 4515.48,5715 4550.77,5750.29 4714.83,5750.29 4736.55,5728.56 4823.47,5728.56 4870.7,5775.8 4870.7,6289.84 4894.28,6313.41 5130,6313.41 5143.65,6299.77 5143.65,6255.54 5097.05,6208.94 5097.05,6208.03 5096.43,6207.41 5096.43,6120.68 5150.85,6066.26 v1(5180,6066.26)
  Bottom Layer w10: v1(5180,6066.26) FPC1.22@5254.35,6066.26
FMC_D11: FPC1.21 U44.67 | length 1637.1
  Inner2 w10: v1(4468.33,5744.65) 4475.72,5737.26 4476.72,5737.26 4482.4,5731.59 4509.47,5731.59 4544.15,5766.27 4721.45,5766.27 4743.17,5744.55 4816.85,5744.55 4854.72,5782.42 4854.72,6299.72 4884.4,6329.4 5140.6,6329.4 5159.63,6310.37 5159.63,6248.92 5113.03,6202.32 5113.03,6201.41 5112.41,6200.79 5112.41,6131.54 5112.79,6131.16 5112.79,6126.92 5156.38,6083.34 5177.4,6083.34 v1(5180,6085.94)
  Bottom Layer w10: v1(5180,6085.94) FPC1.21@5254.35,6085.94
FMC_D12: FPC1.20 U44.68 | length 1638.7
  Inner2 w10: v1(4482.25,5758.57) 4488.63,5752.19 4502.46,5752.19 4537.14,5786.87 4723.45,5786.87 4749.79,5760.53 4810.23,5760.53 4838.73,5789.04 4838.73,6325.61 4858.51,6345.38 5165.61,6345.38 5175.61,6335.38 5175.61,6242.3 5129.02,6195.7 5129.02,6194.79 5128.39,6194.17 5128.39,6138.16 5160.84,6105.72 5171.75,6105.72 5172.46,6105.01 5179.38,6105.01 v1(5180,6105.63)
  Bottom Layer w10: v1(5180,6105.63) FPC1.20@5254.35,6105.63
FMC_D13: FPC1.19 U44.77 | length 1657.1
  Inner2 w10: v1(4740,5835) 4740,5801.39 4764.88,5776.52 4803.61,5776.52 4822.75,5795.66 4822.75,6377.75 4963.03,6518.03 5046.97,6518.03 5192.22,6372.78 5192.22,6236.3 5145,6189.08 5145,6148.39 5168.08,6125.31 v1(5180,6125.31)
  Bottom Layer w10: U44.77@4707.75,5758.57 4740,5790.82 v1(4740,5835) ; v1(5180,6125.31) FPC1.19@5254.35,6125.31
FMC_D14: FPC1.18 U44.78 | length 1651.9
  Inner2 w10: v1(4762.5,5802.5) 4768.74,5802.5 4778.74,5792.5 4796.99,5792.5 4806.76,5802.28 4806.76,6457.92 4882.86,6534.02 5110.81,6534.02 5208.21,6436.62 5208.21,6223.21 5160.98,6175.98 5160.98,6160.09 5176.07,6145 v1(5180,6145)
  Bottom Layer w10: U44.78@4721.67,5744.65 4762.5,5785.48 v1(4762.5,5802.5) ; v1(5180,6145) FPC1.18@5254.35,6145
FMC_D15: FPC1.17 U44.79 | length 1706
  Inner2 w10: v1(4756.69,5822.5) 4756.69,6408.09 4776.69,6428.09 4776.69,6481.69 4845,6550 5155,6550 5225,6480 5225,6209.68 v1(5180,6164.68)
  Bottom Layer w10: U44.79@4735.59,5730.74 4735.59,5735.24 4779.19,5778.84 4779.19,5809.41 4766.11,5822.5 v1(4756.69,5822.5) ; v1(5180,6164.68) FPC1.17@5254.35,6164.68
FMC_NE1: FPC1.38 U44.97 | length 1659.7
  Inner2 w10: v1(5027.13,5520.1) 5027.23,5520 5190,5520 v1(5330,5380)
  Bottom Layer w10: U44.97@4986.14,5480.19 5026.05,5520.1 v1(5027.13,5520.1) ; FPC1.38@5254.35,5751.3 5311.1,5751.3 5507.4,5555 5532.4,5555 5539.47,5562.07 5539.47,5662.93 5546.54,5670 5592.4,5670 5599.47,5662.93 5599.47,5562.07 5630,5531.54 5630,5485 5605,5460 5568.52,5460 5561.45,5452.93 5561.45,5373.21 5554.38,5366.14 5508.52,5366.14 5501.45,5373.21 5501.45,5452.93 5494.38,5460 5475,5460 5395,5380 v1(5330,5380)
FMC_NOE: FPC1.35 U44.118 | length 1683.4
  Inner2 w10: v1(5072.77,5008.31) 5072.77,5017.48 5224.15,5168.86 5323.86,5168.86 5331.36,5161.36 5341.36,5161.36 5373.79,5193.79 5373.79,5203.79 5366.29,5211.29 5366.29,5221.29 5398.71,5253.71 5408.71,5253.71 5416.21,5246.21 5426.21,5246.21 5458.64,5278.64 5458.64,5288.64 5451.14,5296.14 5451.14,5306.14 5475,5330 5475,5390.4 5467.93,5397.47 5377.07,5397.47 5370,5404.54 5370,5450.4 5377.07,5457.47 5467.93,5457.47 5475,5464.54 5475,5510.4 5467.93,5517.47 5377.07,5517.47 5370,5524.54 5370,5570.4 5377.07,5577.47 5407.47,5577.47 5450,5620 v1(5475,5620)
  Bottom Layer w10: U44.118@5013.98,5087.65 5013.98,5083.14 5042.56,5054.56 5042.56,5027.44 5061.69,5008.31 v1(5072.77,5008.31) ; FPC1.35@5254.35,5810.35 5303.26,5810.35 5475,5638.61 v1(5475,5620)
FMC_NWE: FPC1.36 U44.119 | length 1621.6
  Inner2 w10: v1(5030.7,5014.29) 5030.7,5042.61 5079.92,5091.83 5124.52,5091.83 5144.65,5111.96 5144.65,5156.56 5180.02,5191.94 5180.02,5331.27 5187.09,5338.34 5232.95,5338.34 5240.02,5331.27 5240.02,5276.77 5247.09,5269.7 5292.95,5269.7 5300.02,5276.77 5300.02,5331.27 5307.09,5338.34 5352.95,5338.34 5360.02,5331.27 5360.02,5276.77 5367.09,5269.7 5399.7,5269.7 5430,5300 5430,5355 5403.51,5381.49 5370.45,5381.49 5354.02,5397.92 5354.02,5577.02 5372,5595 5395,5595 v1(5445,5645)
  Bottom Layer w10: U44.119@5000.06,5073.73 5000.06,5069.22 5026.58,5042.7 5026.58,5018.41 v1(5030.7,5014.29) ; FPC1.36@5254.35,5790.67 5299.33,5790.67 v1(5445,5645)
FS_A: U44.3 U61.10 | length 3088.6
  Top Layer w10: v1(4475.7,4954.3) 4486.7,4954.3 4500.65,4968.25 4500.65,5094.17 4506.48,5100 v1(4515,5100) ; v1(4578.21,5113.31) 4743.83,5278.93 4743.83,5406.17 4704.04,5445.96 4523.83,5445.96 4498.03,5471.76 4498.03,5538.03 4555,5595 4620.34,5595 4710,5684.66 4710,5818.79 4684.02,5844.77 4684.02,5870 4669.02,5885 4568.43,5885 4495,5958.43 4495,6226.57 4548.43,6280 v1(4685,6280)
  Inner2 w10: v1(4515,5100) 4564.9,5100 v1(4578.21,5113.31)
  Inner3 w10: v1(4462.8,4715.99) 4462.8,4767.8 4485,4790 4682.88,4790 4695,4802.12 4695,4892.17 4665.03,4922.14 4507.86,4922.14 v1(4475.7,4954.3)
  Bottom Layer w10: v1(4462.8,4715.99) 4472.8,4725.98 4482.48,4725.98 U44.3@4510.09,4753.59 ; v1(4685,6280) 4705,6280 4750,6325 4805,6325 4870,6390 U61.10@4914.33,6390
